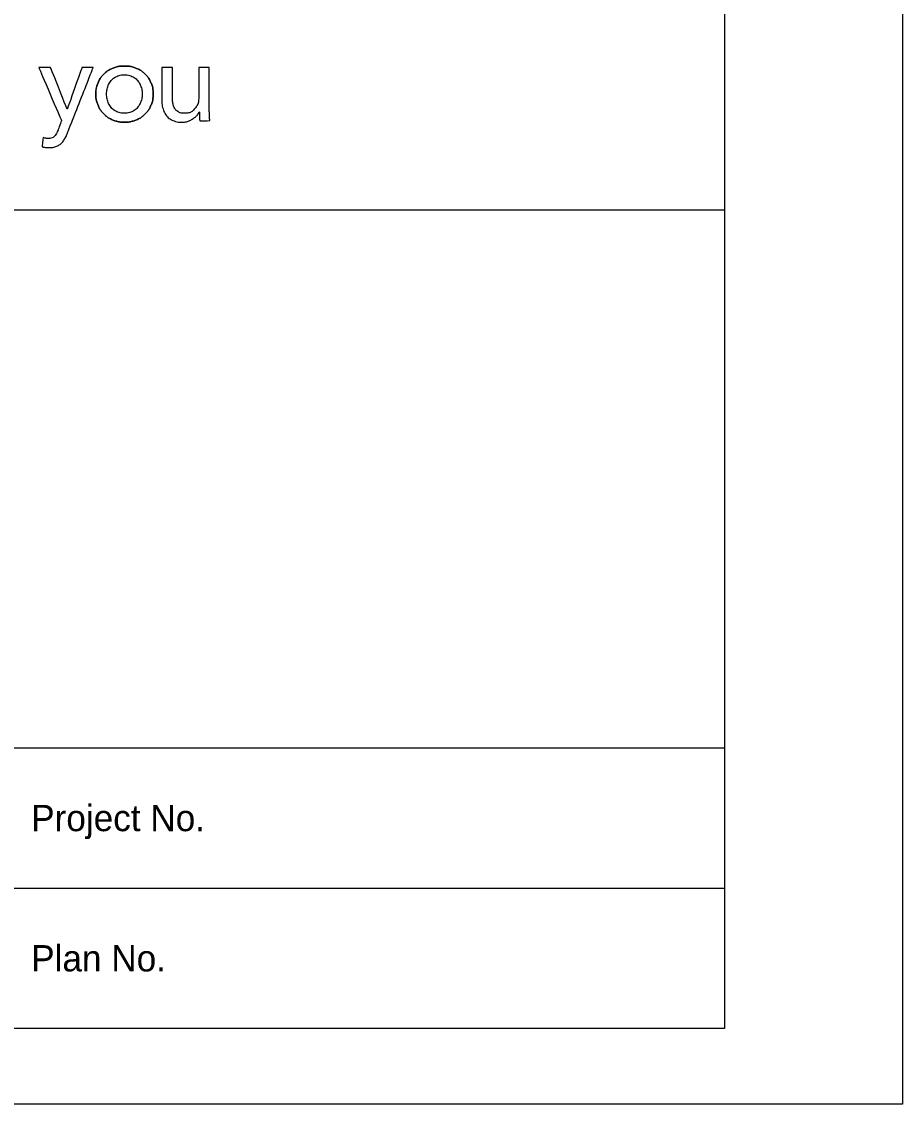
# Model space of a CAD drawing. Extents: x 612883 to 613093, y 4825734 to 4825879.
# Drawn here: x 613078.07 to 613093.15, y 4825733.63 to 4825752.15 of the extents above; entities that cross this region are included whole.
import ezdxf

# ---------------------------------------------------------------- set-up
doc = ezdxf.new("R2010")
doc.units = 0
for name, color, linetype in [('G-ANNO-TTLB-TEXT', 7, 'Continuous'), ('G-TTLB-LOGO', 7, 'Continuous'), ('G-TTLB-OTLN', 7, 'Continuous'), ('G-TTLB-OTLN-PB', 7, 'Continuous')]:
    doc.layers.add(name, color=color, linetype=linetype)

msp = doc.modelspace()

# ---------------------------------------------------------------- linework, layer by layer
at = {"layer": 'G-TTLB-LOGO'}
for points in [[(613078.845, 4825750.655), (613078.845, 4825750.655), (613078.849, 4825750.655), (613078.849, 4825750.655), (613078.849, 4825750.655), (613079.101, 4825751.369), (613079.101, 4825751.369), (613079.101, 4825751.369), (613079.293, 4825751.369), (613079.293, 4825751.369), (613079.293, 4825751.369), (613078.851, 4825750.244), (613078.851, 4825750.244), (613078.836, 4825750.206), (613078.819, 4825750.171), (613078.801, 4825750.141), (613078.783, 4825750.111), (613078.762, 4825750.086), (613078.738, 4825750.064), (613078.713, 4825750.043), (613078.685, 4825750.027), (613078.652, 4825750.016), (613078.62, 4825750.004), (613078.581, 4825749.998), (613078.536, 4825749.998), (613078.517, 4825749.998), (613078.497, 4825749.999), (613078.478, 4825750.001), (613078.458, 4825750.003), (613078.438, 4825750.007), (613078.417, 4825750.012), (613078.417, 4825750.012), (613078.434, 4825750.171), (613078.434, 4825750.171), (613078.465, 4825750.161), (613078.495, 4825750.156), (613078.525, 4825750.156), (613078.572, 4825750.156), (613078.607, 4825750.169), (613078.63, 4825750.195), (613078.653, 4825750.221), (613078.674, 4825750.259), (613078.694, 4825750.307), (613078.694, 4825750.307), (613078.751, 4825750.459), (613078.751, 4825750.459), (613078.751, 4825750.459), (613078.361, 4825751.369), (613078.361, 4825751.369), (613078.361, 4825751.369), (613078.563, 4825751.369), (613078.563, 4825751.369), (613078.563, 4825751.369), (613078.845, 4825750.655), (613078.845, 4825750.655)], [(613078.845, 4825750.655), (613078.845, 4825750.655), (613078.849, 4825750.655), (613078.849, 4825750.655), (613078.849, 4825750.655), (613079.101, 4825751.369), (613079.101, 4825751.369), (613079.101, 4825751.369), (613079.293, 4825751.369), (613079.293, 4825751.369), (613079.293, 4825751.369), (613078.851, 4825750.244), (613078.851, 4825750.244), (613078.836, 4825750.206), (613078.819, 4825750.171), (613078.801, 4825750.141), (613078.783, 4825750.111), (613078.762, 4825750.086), (613078.738, 4825750.064), (613078.713, 4825750.043), (613078.685, 4825750.027), (613078.652, 4825750.016), (613078.62, 4825750.004), (613078.581, 4825749.998), (613078.536, 4825749.998), (613078.517, 4825749.998), (613078.497, 4825749.999), (613078.478, 4825750.001), (613078.458, 4825750.003), (613078.438, 4825750.007), (613078.417, 4825750.012), (613078.417, 4825750.012), (613078.434, 4825750.171), (613078.434, 4825750.171), (613078.465, 4825750.161), (613078.495, 4825750.156), (613078.525, 4825750.156), (613078.572, 4825750.156), (613078.607, 4825750.169), (613078.63, 4825750.195), (613078.653, 4825750.221), (613078.674, 4825750.259), (613078.694, 4825750.307), (613078.694, 4825750.307), (613078.751, 4825750.459), (613078.751, 4825750.459), (613078.751, 4825750.459), (613078.361, 4825751.369), (613078.361, 4825751.369), (613078.361, 4825751.369), (613078.563, 4825751.369), (613078.563, 4825751.369), (613078.563, 4825751.369), (613078.845, 4825750.655), (613078.845, 4825750.655)], [(613080.32, 4825750.916), (613080.32, 4825750.846), (613080.307, 4825750.781), (613080.282, 4825750.722), (613080.257, 4825750.663), (613080.223, 4825750.612), (613080.178, 4825750.57), (613080.135, 4825750.527), (613080.082, 4825750.493), (613080.022, 4825750.47), (613079.962, 4825750.446), (613079.897, 4825750.434), (613079.828, 4825750.434), (613079.759, 4825750.434), (613079.694, 4825750.446), (613079.634, 4825750.47), (613079.574, 4825750.493), (613079.522, 4825750.527), (613079.479, 4825750.57), (613079.435, 4825750.612), (613079.401, 4825750.663), (613079.376, 4825750.722), (613079.351, 4825750.781), (613079.338, 4825750.846), (613079.338, 4825750.916), (613079.338, 4825750.987), (613079.351, 4825751.051), (613079.376, 4825751.109), (613079.401, 4825751.167), (613079.435, 4825751.218), (613079.479, 4825751.26), (613079.522, 4825751.302), (613079.574, 4825751.335), (613079.634, 4825751.359), (613079.694, 4825751.382), (613079.759, 4825751.394), (613079.828, 4825751.394), (613079.897, 4825751.394), (613079.962, 4825751.382), (613080.022, 4825751.359), (613080.082, 4825751.335), (613080.135, 4825751.302), (613080.178, 4825751.26), (613080.223, 4825751.218), (613080.257, 4825751.167), (613080.282, 4825751.109), (613080.307, 4825751.051), (613080.32, 4825750.987), (613080.32, 4825750.916)], [(613079.35, 4825751.026), (613079.356, 4825751.055), (613079.364, 4825751.083), (613079.376, 4825751.109), (613079.401, 4825751.167), (613079.435, 4825751.218), (613079.479, 4825751.26), (613079.522, 4825751.302), (613079.574, 4825751.335), (613079.634, 4825751.359), (613079.694, 4825751.382), (613079.759, 4825751.394), (613079.828, 4825751.394), (613079.897, 4825751.394), (613079.962, 4825751.382), (613080.022, 4825751.359), (613080.082, 4825751.335), (613080.135, 4825751.302), (613080.178, 4825751.26), (613080.223, 4825751.218), (613080.257, 4825751.167), (613080.282, 4825751.109), (613080.307, 4825751.051), (613080.32, 4825750.987), (613080.32, 4825750.916)], [(613080.132, 4825750.915), (613080.132, 4825750.959), (613080.125, 4825751), (613080.111, 4825751.04), (613080.098, 4825751.079), (613080.078, 4825751.114), (613080.053, 4825751.144), (613080.027, 4825751.174), (613079.995, 4825751.198), (613079.957, 4825751.216), (613079.919, 4825751.234), (613079.876, 4825751.243), (613079.827, 4825751.243), (613079.778, 4825751.243), (613079.735, 4825751.234), (613079.697, 4825751.216), (613079.659, 4825751.198), (613079.627, 4825751.174), (613079.602, 4825751.144), (613079.576, 4825751.114), (613079.556, 4825751.079), (613079.543, 4825751.04), (613079.529, 4825751), (613079.523, 4825750.959), (613079.523, 4825750.915), (613079.523, 4825750.872), (613079.529, 4825750.83), (613079.543, 4825750.791), (613079.556, 4825750.751), (613079.576, 4825750.716), (613079.602, 4825750.685), (613079.627, 4825750.655), (613079.659, 4825750.631), (613079.697, 4825750.613), (613079.735, 4825750.595), (613079.778, 4825750.586), (613079.827, 4825750.586), (613079.876, 4825750.586), (613079.919, 4825750.595), (613079.957, 4825750.613), (613079.995, 4825750.631), (613080.027, 4825750.655), (613080.053, 4825750.685), (613080.078, 4825750.716), (613080.098, 4825750.751), (613080.111, 4825750.791), (613080.125, 4825750.83), (613080.132, 4825750.872), (613080.132, 4825750.915)], [(613080.132, 4825750.915), (613080.132, 4825750.959), (613080.125, 4825751), (613080.111, 4825751.04), (613080.098, 4825751.079), (613080.078, 4825751.114), (613080.053, 4825751.144), (613080.027, 4825751.174), (613079.995, 4825751.198), (613079.957, 4825751.216), (613079.919, 4825751.234), (613079.876, 4825751.243), (613079.827, 4825751.243), (613079.778, 4825751.243), (613079.735, 4825751.234), (613079.697, 4825751.216), (613079.659, 4825751.198), (613079.627, 4825751.174), (613079.602, 4825751.144), (613079.576, 4825751.114), (613079.556, 4825751.079), (613079.543, 4825751.04), (613079.529, 4825751), (613079.523, 4825750.959), (613079.523, 4825750.915), (613079.523, 4825750.872), (613079.529, 4825750.83), (613079.543, 4825750.791), (613079.556, 4825750.751), (613079.576, 4825750.716), (613079.602, 4825750.685), (613079.627, 4825750.655), (613079.659, 4825750.631), (613079.697, 4825750.613), (613079.735, 4825750.595), (613079.778, 4825750.586), (613079.827, 4825750.586), (613079.876, 4825750.586), (613079.919, 4825750.595), (613079.957, 4825750.613), (613079.995, 4825750.631), (613080.027, 4825750.655), (613080.053, 4825750.685), (613080.078, 4825750.716), (613080.098, 4825750.751), (613080.111, 4825750.791), (613080.125, 4825750.83), (613080.132, 4825750.872), (613080.132, 4825750.915)], [(613081.118, 4825750.459), (613081.115, 4825750.482), (613081.113, 4825750.508), (613081.112, 4825750.537), (613081.111, 4825750.566), (613081.11, 4825750.59), (613081.11, 4825750.609), (613081.11, 4825750.609), (613081.106, 4825750.609), (613081.106, 4825750.609), (613081.083, 4825750.56), (613081.044, 4825750.519), (613080.99, 4825750.485), (613080.935, 4825750.451), (613080.875, 4825750.434), (613080.808, 4825750.434), (613080.749, 4825750.434), (613080.698, 4825750.444), (613080.656, 4825750.463), (613080.613, 4825750.482), (613080.577, 4825750.509), (613080.55, 4825750.543), (613080.522, 4825750.577), (613080.502, 4825750.616), (613080.488, 4825750.661), (613080.475, 4825750.706), (613080.468, 4825750.754), (613080.468, 4825750.805), (613080.468, 4825750.805), (613080.468, 4825751.369), (613080.468, 4825751.369), (613080.468, 4825751.369), (613080.649, 4825751.369), (613080.649, 4825751.369), (613080.649, 4825751.369), (613080.649, 4825750.866), (613080.649, 4825750.866), (613080.649, 4825750.829), (613080.652, 4825750.794), (613080.657, 4825750.76), (613080.663, 4825750.726), (613080.674, 4825750.696), (613080.689, 4825750.67), (613080.705, 4825750.645), (613080.726, 4825750.624), (613080.753, 4825750.609), (613080.78, 4825750.594), (613080.814, 4825750.586), (613080.856, 4825750.586), (613080.929, 4825750.586), (613080.988, 4825750.613), (613081.033, 4825750.667), (613081.078, 4825750.722), (613081.1, 4825750.794), (613081.1, 4825750.885), (613081.1, 4825750.885), (613081.1, 4825751.369), (613081.1, 4825751.369), (613081.1, 4825751.369), (613081.281, 4825751.369), (613081.281, 4825751.369), (613081.281, 4825751.369), (613081.281, 4825750.655), (613081.281, 4825750.655), (613081.281, 4825750.631), (613081.281, 4825750.599), (613081.283, 4825750.561), (613081.284, 4825750.522), (613081.286, 4825750.488), (613081.289, 4825750.459), (613081.289, 4825750.459), (613081.118, 4825750.459), (613081.118, 4825750.459)], [(613081.118, 4825750.459), (613081.115, 4825750.482), (613081.113, 4825750.508), (613081.112, 4825750.537), (613081.111, 4825750.566), (613081.11, 4825750.59), (613081.11, 4825750.609), (613081.11, 4825750.609), (613081.106, 4825750.609), (613081.106, 4825750.609), (613081.083, 4825750.56), (613081.044, 4825750.519), (613080.99, 4825750.485), (613080.935, 4825750.451), (613080.875, 4825750.434), (613080.808, 4825750.434), (613080.749, 4825750.434), (613080.698, 4825750.444), (613080.656, 4825750.463), (613080.613, 4825750.482), (613080.577, 4825750.509), (613080.55, 4825750.543), (613080.522, 4825750.577), (613080.502, 4825750.616), (613080.488, 4825750.661), (613080.475, 4825750.706), (613080.468, 4825750.754), (613080.468, 4825750.805), (613080.468, 4825750.805), (613080.468, 4825751.369), (613080.468, 4825751.369), (613080.468, 4825751.369), (613080.649, 4825751.369), (613080.649, 4825751.369), (613080.649, 4825751.369), (613080.649, 4825750.866), (613080.649, 4825750.866), (613080.649, 4825750.829), (613080.652, 4825750.794), (613080.657, 4825750.76), (613080.663, 4825750.726), (613080.674, 4825750.696), (613080.689, 4825750.67), (613080.705, 4825750.645), (613080.726, 4825750.624), (613080.753, 4825750.609), (613080.78, 4825750.594), (613080.814, 4825750.586), (613080.856, 4825750.586), (613080.929, 4825750.586), (613080.988, 4825750.613), (613081.033, 4825750.667), (613081.078, 4825750.722), (613081.1, 4825750.794), (613081.1, 4825750.885), (613081.1, 4825750.885), (613081.1, 4825751.369), (613081.1, 4825751.369), (613081.1, 4825751.369), (613081.281, 4825751.369), (613081.281, 4825751.369), (613081.281, 4825751.369), (613081.281, 4825750.655), (613081.281, 4825750.655), (613081.281, 4825750.631), (613081.281, 4825750.599), (613081.283, 4825750.561), (613081.284, 4825750.522), (613081.286, 4825750.488), (613081.289, 4825750.459), (613081.289, 4825750.459), (613081.118, 4825750.459), (613081.118, 4825750.459)], [(613080.32, 4825750.916), (613080.32, 4825750.846), (613080.307, 4825750.781), (613080.282, 4825750.722), (613080.257, 4825750.663), (613080.223, 4825750.612), (613080.178, 4825750.57), (613080.135, 4825750.527), (613080.082, 4825750.493), (613080.022, 4825750.47), (613079.962, 4825750.446), (613079.897, 4825750.434), (613079.828, 4825750.434), (613079.759, 4825750.434), (613079.694, 4825750.446), (613079.634, 4825750.47), (613079.574, 4825750.493), (613079.522, 4825750.527), (613079.479, 4825750.57), (613079.435, 4825750.612), (613079.401, 4825750.663), (613079.376, 4825750.722), (613079.351, 4825750.781), (613079.338, 4825750.846), (613079.338, 4825750.916), (613079.338, 4825750.955), (613079.342, 4825750.991), (613079.35, 4825751.026)]]:
    msp.add_open_spline(points, degree=3, dxfattribs=at)
at = {"layer": 'G-TTLB-OTLN'}
for p, q in [((613090.1, 4825748.926), (613058.399, 4825748.926)), ((613058.399, 4825739.726), (613090.1, 4825739.726)), ((613077.723, 4825737.326), (613090.1, 4825737.326))]:
    msp.add_line(p, q, dxfattribs=at)
msp.add_lwpolyline([(612893.053, 4825869.211), (613090.1, 4825869.211), (613090.1, 4825734.927), (612893.053, 4825734.927)], close=True, dxfattribs=at)
at = {"layer": 'G-TTLB-OTLN-PB'}
for p, q in [((613093.146, 4825736.627), (613093.146, 4825733.627)), ((613093.146, 4825733.627), (613090.5, 4825733.627))]:
    msp.add_line(p, q, dxfattribs=at)
msp.add_lwpolyline([(612882.799, 4825870.511), (613093.146, 4825870.511), (613093.146, 4825733.627), (612882.799, 4825733.627)], close=True, dxfattribs=at)

# ---------------------------------------------------------------- texts
at = {"layer": 'G-ANNO-TTLB-TEXT'}
for s, p in [('Project No.', (613078.231, 4825738.301)), ('Plan No.', (613078.231, 4825735.901))]:
    msp.add_text(s, height=0.45, dxfattribs=at).set_placement(p)

doc.saveas('drawing.dxf')
